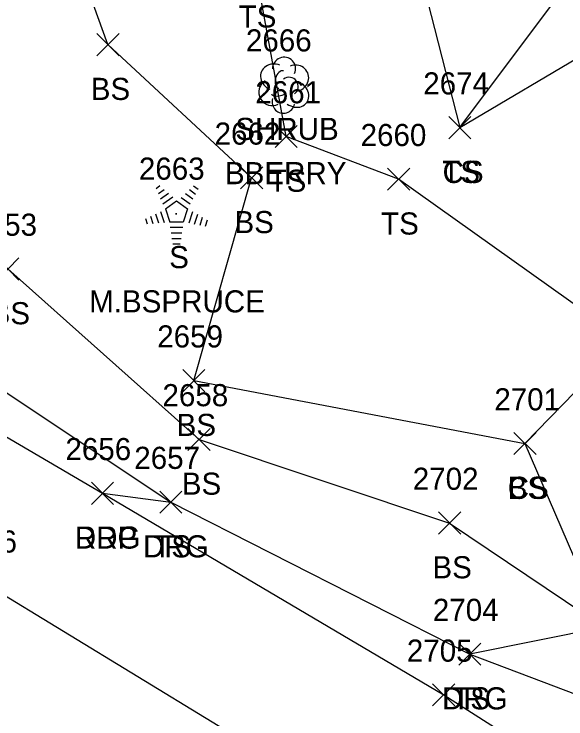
# Model space of a CAD drawing. Extents: x 1499292 to 1501024, y 534584 to 538043.
# Drawn here: x 1499668.2 to 1499718.2, y 537795.2 to 537858.9 of the extents above; entities that cross this region are included whole.
import ezdxf

# ---------------------------------------------------------------- set-up
doc = ezdxf.new("R2010")
doc.units = 0
for name, color, linetype in [('L_A', 7, 'Continuous'), ('L_C', 7, 'Continuous'), ('L_I', 7, 'Continuous'), ('L_TIC', 7, 'Continuous'), ('LELB', 7, 'Continuous'), ('LSH', 7, 'Continuous'), ('LTC', 7, 'Continuous'), ('P_A', 7, 'Continuous'), ('P_I', 7, 'Continuous'), ('P_TIC', 7, 'Continuous'), ('PET', 7, 'Continuous'), ('PRC', 7, 'Continuous'), ('R_A', 7, 'Continuous'), ('R_I', 7, 'Continuous'), ('R_TIC', 7, 'Continuous'), ('RDG', 7, 'Continuous')]:
    doc.layers.add(name, color=color, linetype=linetype)

msp = doc.modelspace()

# ---------------------------------------------------------------- linework, layer by layer
at = {"layer": 'L_TIC'}
for points in [[(1499675.722, 537855.181), (1499677.722, 537857.181)], [(1499677.722, 537855.181), (1499675.722, 537857.181)], [(1499707.557, 537847.679), (1499709.557, 537849.679)], [(1499709.557, 537847.679), (1499707.557, 537849.679)], [(1499707.557, 537847.679), (1499709.557, 537849.679)], [(1499709.557, 537847.679), (1499707.557, 537849.679)], [(1499691.841, 537846.878), (1499693.841, 537848.878)], [(1499693.841, 537846.878), (1499691.841, 537848.878)], [(1499688.723, 537843.141), (1499690.723, 537845.141)], [(1499690.723, 537843.141), (1499688.723, 537845.141)], [(1499702.022, 537843.013), (1499704.022, 537845.013)], [(1499704.022, 537843.013), (1499702.022, 537845.013)], [(1499702.022, 537843.013), (1499704.022, 537845.013)], [(1499704.022, 537843.013), (1499702.022, 537845.013)], [(1499666.661, 537834.904), (1499668.661, 537836.904)], [(1499668.661, 537834.904), (1499666.661, 537836.904)], [(1499683.494, 537824.807), (1499685.494, 537826.807)], [(1499685.494, 537824.807), (1499683.494, 537826.807)], [(1499683.494, 537824.807), (1499685.494, 537826.807)], [(1499685.494, 537824.807), (1499683.494, 537826.807)], [(1499683.96, 537819.495), (1499685.96, 537821.495)], [(1499685.96, 537819.495), (1499683.96, 537821.495)], [(1499713.453, 537819.121), (1499715.453, 537821.121)], [(1499715.453, 537819.121), (1499713.453, 537821.121)], [(1499713.453, 537819.121), (1499715.453, 537821.121)], [(1499715.453, 537819.121), (1499713.453, 537821.121)], [(1499681.408, 537813.83), (1499683.408, 537815.83)], [(1499683.408, 537813.83), (1499681.408, 537815.83)], [(1499706.639, 537811.939), (1499708.639, 537813.939)], [(1499708.639, 537811.939), (1499706.639, 537813.939)], [(1499708.457, 537800.089), (1499710.457, 537802.089)], [(1499710.457, 537800.089), (1499708.457, 537802.089)]]:
    msp.add_lwpolyline(points, dxfattribs=at)
at = {"layer": 'LELB'}
for points in [[(1499684.494, 537825.807), (1499689.723, 537844.141), (1499676.722, 537856.181), (1499672.818, 537866.992), (1499670.986, 537885.024), (1499680.161, 537901.686)], [(1499703.022, 537844.013), (1499692.841, 537847.878), (1499690.135, 537862.728), (1499685.108, 537869.508), (1499680.161, 537901.686)], [(1499707.743, 537886.157), (1499703.659, 537867.78), (1499708.557, 537848.679), (1499744.663, 537870.04), (1499731.719, 537843.464), (1499723.516, 537829.446), (1499714.453, 537820.121), (1499721.619, 537803.525)], [(1499708.557, 537848.679), (1499720.838, 537865.093), (1499729.714, 537876.829), (1499751.905, 537875.83), (1499761.341, 537868.452)], [(1499625.53, 537865.077), (1499619.548, 537854.557), (1499626.141, 537847.711), (1499635.935, 537842.316), (1499651.071, 537835.781), (1499662.043, 537828.35), (1499682.408, 537814.83)], [(1499627.747, 537855.268), (1499639.004, 537847.929), (1499652.639, 537838.691), (1499667.661, 537835.904), (1499684.96, 537820.495), (1499707.639, 537812.939), (1499721.619, 537803.525), (1499733.304, 537792.08), (1499740.748, 537784.702), (1499753.291, 537774.66), (1499768.462, 537764.036)], [(1499723.516, 537829.446), (1499703.022, 537844.013)], [(1499684.494, 537825.807), (1499714.453, 537820.121)], [(1499721.619, 537803.525), (1499709.457, 537801.089)]]:
    msp.add_lwpolyline(points, dxfattribs=at)
at = {"layer": 'LSH'}
msp.add_line((1499692.611, 537852.564), (1499692.611, 537852.564), dxfattribs=at)
msp.add_line((1499692.611, 537852.564), (1499692.611, 537852.564), dxfattribs=at)
msp.add_arc((1499692.658, 537853.998), 1.047, 335.52715, 180.95627, dxfattribs=at)
for centre, major_axis, ratio, start_param, end_param in [((1499691.82, 537853.231), (1.21, -0.512), 0.895232, 1.570796, 4.712389), ((1499693.653, 537853.148), (-1.141, -0.483), 0.949671, 1.570796, 4.712389), ((1499692.403, 537853.022), (-0.208, -0.792), 0.645439, 3.141593, 6.283185), ((1499691.528, 537851.855), (0.584, -1.042), 0.959034, 3.141593, 6.283185), ((1499693.111, 537852.397), (-0.5, 0.667), 0.989748, 3.141593, 6.283185), ((1499693.612, 537851.731), (-1.09, 0.792), 0.841452, 1.570796, 4.712389), ((1499692.153, 537851.814), (-0.625, -0.083), 0.423636, 0, 3.141593), ((1499692.612, 537851.064), (0.265, 1.061), 0.942809, 1.570796, 4.712389)]:
    msp.add_ellipse(centre, major_axis=major_axis, ratio=ratio, start_param=start_param, end_param=end_param, dxfattribs=at)
at = {"layer": 'LTC'}
for p, q in [((1499681.07, 537843.182), (1499681.424, 537843.44)), ((1499684.468, 537843.423), (1499684.887, 537843.118)), ((1499681.279, 537842.717), (1499681.808, 537843.101)), ((1499681.489, 537842.251), (1499682.192, 537842.762)), ((1499683.726, 537842.726), (1499684.405, 537842.232)), ((1499684.097, 537843.074), (1499684.646, 537842.675)), ((1499681.698, 537841.785), (1499682.577, 537842.423)), ((1499681.923, 537841.33), (1499682.935, 537842.065)), ((1499682.935, 537842.065), (1499683.932, 537841.34)), ((1499683.355, 537842.378), (1499684.164, 537841.789)), ((1499681.013, 537840.895), (1499681.284, 537840.059)), ((1499681.468, 537841.111), (1499681.799, 537840.092)), ((1499681.923, 537841.33), (1499682.31, 537840.137)), ((1499683.932, 537841.34), (1499683.54, 537840.137)), ((1499684.369, 537841.069), (1499684.031, 537840.029)), ((1499684.814, 537840.818), (1499684.526, 537839.934)), ((1499680.102, 537840.461), (1499680.254, 537839.993)), ((1499680.557, 537840.678), (1499680.769, 537840.026)), ((1499683.54, 537840.137), (1499682.31, 537840.137)), ((1499685.258, 537840.568), (1499685.021, 537839.839)), ((1499685.702, 537840.318), (1499685.516, 537839.744)), ((1499683.502, 537839.637), (1499682.357, 537839.637)), ((1499683.418, 537839.137), (1499682.43, 537839.137)), ((1499683.335, 537838.637), (1499682.503, 537838.637)), ((1499683.251, 537838.137), (1499682.576, 537838.137))]:
    msp.add_line(p, q, dxfattribs=at)
at = {"layer": 'P_TIC'}
for points in [[(1499675.234, 537814.623), (1499677.234, 537816.623)], [(1499677.234, 537814.623), (1499675.234, 537816.623)], [(1499706.101, 537796.403), (1499708.101, 537798.403)], [(1499708.101, 537796.403), (1499706.101, 537798.403)]]:
    msp.add_lwpolyline(points, dxfattribs=at)
at = {"layer": 'PET'}
msp.add_lwpolyline([(1499318.777, 538007.185), (1499356.077, 537991.329), (1499396.207, 537971.039), (1499437.012, 537950.167), (1499476.074, 537929.172), (1499509.306, 537910.677), (1499546.423, 537890.59), (1499566.293, 537879.272), (1499602.082, 537858.76), (1499615.195, 537851.418), (1499643.027, 537835.063), (1499676.234, 537815.623), (1499707.101, 537797.403), (1499725.198, 537785.865), (1499749.466, 537768.587), (1499768.247, 537754.161), (1499782.48, 537740.777), (1499805.279, 537716.472), (1499820.533, 537699.08)], dxfattribs=at)
at = {"layer": 'PRC'}
msp.add_lwpolyline([(1499314.647, 537995.238), (1499351.896, 537980.059), (1499390.853, 537960.785), (1499432.771, 537938.063), (1499470.255, 537918.917), (1499503.529, 537899.736), (1499550.301, 537873.589), (1499594.281, 537849.334), (1499631.071, 537828.01), (1499665.93, 537807.267), (1499699.614, 537786.782), (1499728.317, 537767.815), (1499774.937, 537731.181), (1499796.918, 537710.716), (1499813.912, 537693.068)], dxfattribs=at)
at = {"layer": 'R_TIC'}
for points in [[(1499675.234, 537814.623), (1499677.234, 537816.623)], [(1499677.234, 537814.623), (1499675.234, 537816.623)], [(1499681.408, 537813.83), (1499683.408, 537815.83)], [(1499683.408, 537813.83), (1499681.408, 537815.83)], [(1499708.457, 537800.089), (1499710.457, 537802.089)], [(1499710.457, 537800.089), (1499708.457, 537802.089)], [(1499708.457, 537800.089), (1499710.457, 537802.089)], [(1499710.457, 537800.089), (1499708.457, 537802.089)]]:
    msp.add_lwpolyline(points, dxfattribs=at)
at = {"layer": 'RDG'}
for points in [[(1499709.457, 537801.089), (1499733.304, 537792.08), (1499743.867, 537790.105), (1499751.203, 537789.361), (1499760.905, 537804.652), (1499770.068, 537817.715), (1499787.094, 537803.859), (1499776.944, 537787.425), (1499769.42, 537774.551), (1499769.797, 537771.048), (1499768.462, 537764.036), (1499768.531, 537758.489)], [(1499676.234, 537815.623), (1499682.408, 537814.83), (1499709.457, 537801.089)]]:
    msp.add_lwpolyline(points, dxfattribs=at)

# ---------------------------------------------------------------- texts
at = {"layer": 'L_A'}
for s, p in [('TS', (1499688.544, 537857.728)), ('BS', (1499675.163, 537851.181)), ('SHRUB', (1499688.241, 537847.564)), ('TS', (1499706.967, 537843.679)), ('CS', (1499706.998, 537843.679)), ('TS', (1499691.25, 537842.878)), ('BS', (1499688.164, 537839.141)), ('TS', (1499701.432, 537839.013)), ('TS', (1499701.432, 537839.013)), ('S', (1499682.26, 537835.974)), ('BS', (1499666.102, 537830.904)), ('BS', (1499682.935, 537820.807)), ('BS', (1499682.935, 537820.807)), ('BS', (1499683.401, 537815.495)), ('CS', (1499712.894, 537815.121)), ('BS', (1499712.894, 537815.121)), ('TS', (1499680.818, 537809.83)), ('BS', (1499706.08, 537807.939)), ('TS', (1499707.866, 537796.089))]:
    msp.add_text(s, height=2, dxfattribs=at).set_placement(p)
at = {"layer": 'L_C'}
for s, p in [('BBERRY', (1499687.304, 537843.564)), ('M.BSPRUCE', (1499675.016, 537831.974))]:
    msp.add_text(s, height=2, dxfattribs=at).set_placement(p)
at = {"layer": 'L_I'}
for s, p in [('2666', (1499689.202, 537855.564)), ('2674', (1499705.25, 537851.679)), ('2674', (1499705.25, 537851.679)), ('2661', (1499690.054, 537850.878)), ('2662', (1499686.368, 537847.141)), ('2660', (1499699.581, 537847.013)), ('2660', (1499699.581, 537847.013)), ('2663', (1499679.52, 537843.974)), ('2653', (1499664.354, 537838.904)), ('2659', (1499681.179, 537828.807)), ('2659', (1499681.179, 537828.807)), ('2658', (1499681.653, 537823.495)), ('2701', (1499711.682, 537823.121)), ('2701', (1499711.682, 537823.121)), ('2657', (1499679.101, 537817.83)), ('2702', (1499704.301, 537815.939)), ('2704', (1499706.118, 537804.089))]:
    msp.add_text(s, height=2, dxfattribs=at).set_placement(p)
at = {"layer": 'LTC'}
msp.add_text('.', height=1.037, rotation=270, dxfattribs=at).set_placement((1499682.817, 537841.078))
at = {"layer": 'P_A'}
msp.add_text('RDP', height=2, dxfattribs=at).set_placement((1499673.722, 537810.623))
at = {"layer": 'P_I'}
for s, p in [('2656', (1499672.872, 537818.623)), ('2906', (1499662.537, 537810.267)), ('2705', (1499703.763, 537800.403))]:
    msp.add_text(s, height=2, dxfattribs=at).set_placement(p)
at = {"layer": 'R_A'}
for p in [(1499673.722, 537810.623), (1499679.896, 537809.83), (1499706.945, 537796.089), (1499706.945, 537796.089)]:
    msp.add_text('DRG', height=2, dxfattribs=at).set_placement(p)
at = {"layer": 'R_I'}
for s, p in [('2656', (1499672.872, 537818.623)), ('2657', (1499679.101, 537817.83)), ('2704', (1499706.118, 537804.089)), ('2704', (1499706.118, 537804.089))]:
    msp.add_text(s, height=2, dxfattribs=at).set_placement(p)

doc.saveas('drawing.dxf')
